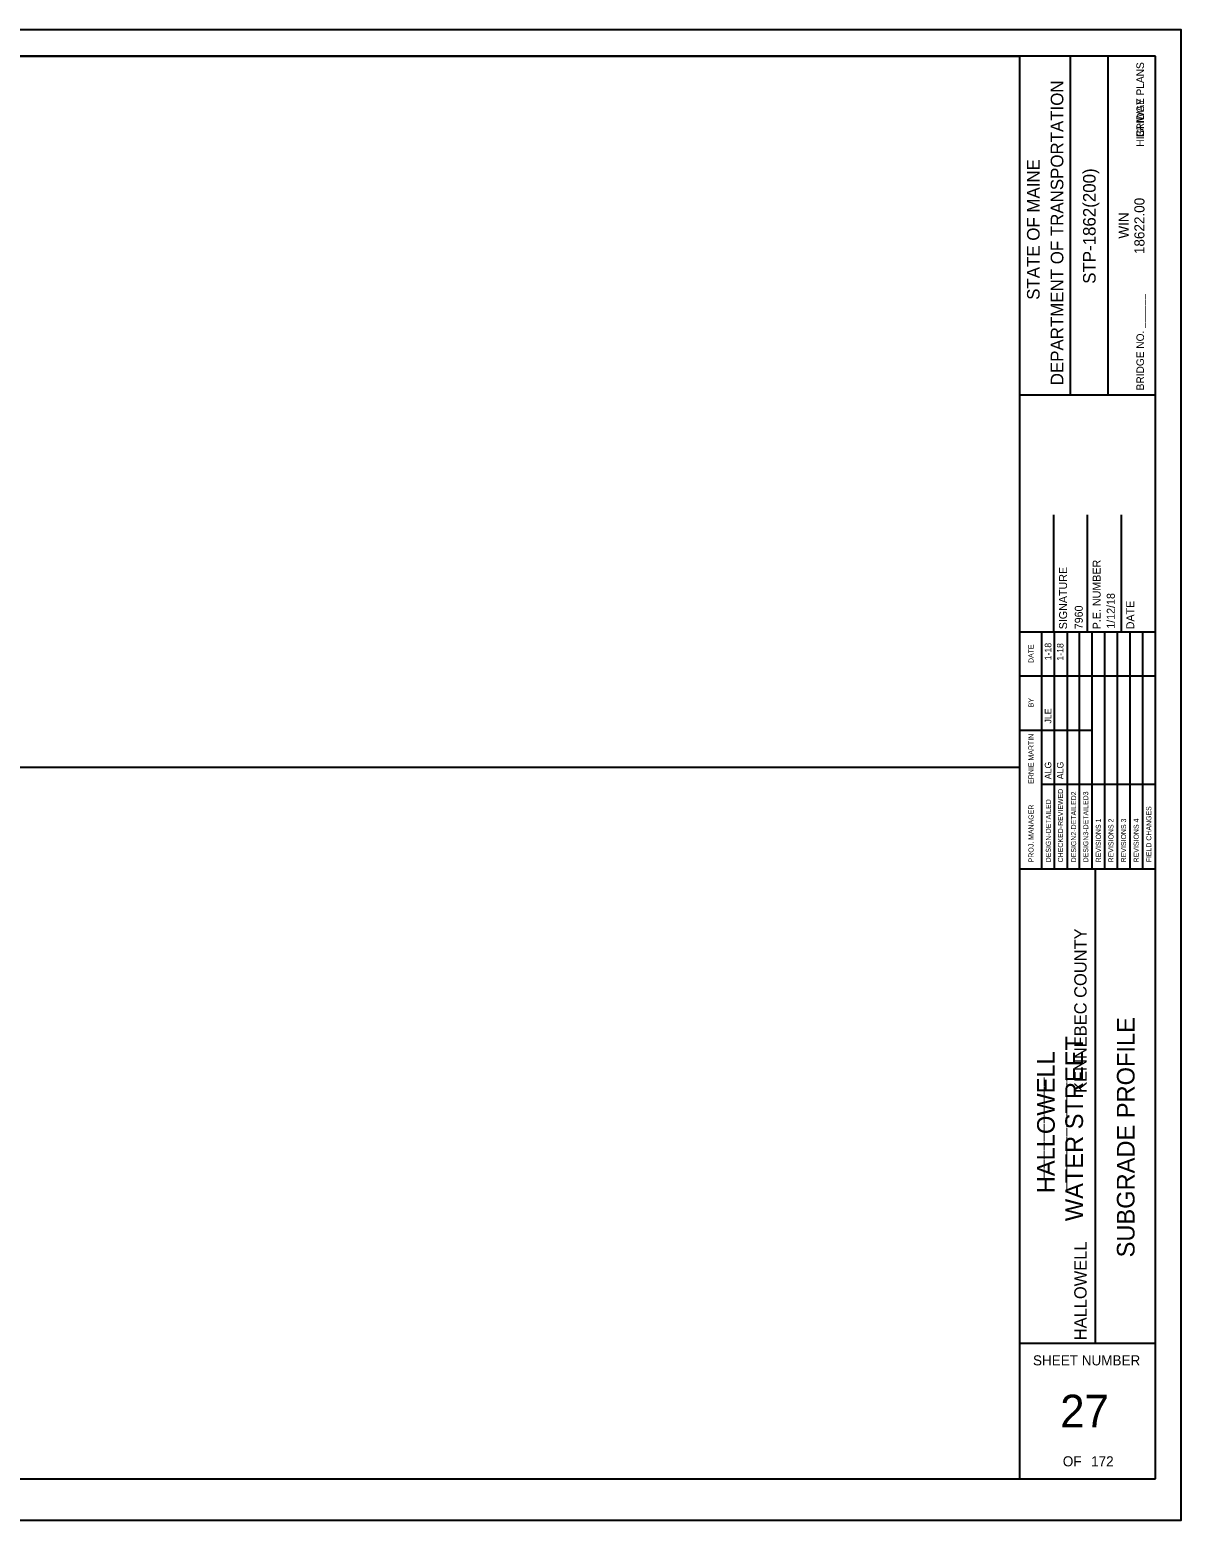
# Model space of a CAD drawing. Extents: x 0 to 850, y 0 to 550.
# Drawn here: x 425 to 850, y 0 to 550 of the extents above; entities that cross this region are included whole.
import ezdxf

# ---------------------------------------------------------------- set-up
doc = ezdxf.new("R2010")
doc.units = 0
for name, color, linetype in [('BORDER', 7, 'Continuous'), ('BRIDGE_TITLE', 7, 'Continuous'), ('Default', 7, 'Continuous'), ('HIGHWAY_TITLE', 7, 'Continuous'), ('PLOT BOUNDARY', 7, 'Continuous')]:
    doc.layers.add(name, color=color, linetype=linetype)

msp = doc.modelspace()

# ---------------------------------------------------------------- linework, layer by layer
at = {"layer": 'BORDER'}
for p, q in [((840.5, 540.32), (40.47, 540.32)), ((790.49, 15.32), (790.49, 540.33)), ((809.14, 415.3), (809.14, 540.3)), ((823.11, 415.3), (823.11, 540.3)), ((840.5, 15.32), (840.5, 540.32)), ((790.5, 415.29), (840.5, 415.29)), ((802.99, 327.83), (802.99, 371.07)), ((815.5, 327.83), (815.5, 371.07)), ((828, 327.83), (828, 371.07)), ((790.49, 327.83), (840.5, 327.83)), ((790.49, 240.33), (840.5, 240.33)), ((818.45, 65.32), (818.45, 240.33)), ((790.49, 65.32), (840.5, 65.32)), ((40.47, 15.3), (840.5, 15.3))]:
    msp.add_line(p, q, dxfattribs=at)
for points in [[(798.57, 311.58), (798.57, 327.83)], [(803.23, 240.34), (803.23, 327.83)], [(807.89, 327.83), (807.89, 240.34)], [(812.55, 240.34), (812.55, 327.83)], [(817.21, 240.34), (817.21, 327.83)], [(821.87, 240.34), (821.87, 327.83)], [(826.52, 240.34), (826.52, 327.83)], [(831.18, 240.34), (831.18, 327.83)], [(835.84, 240.34), (835.84, 327.83)], [(798.57, 240.34), (798.57, 324.3)], [(790.49, 311.58), (840.5, 311.58)], [(790.49, 291.58), (798.57, 291.58)], [(798.57, 291.58), (817.2, 291.58)], [(798.57, 271.58), (840.5, 271.58)]]:
    msp.add_lwpolyline(points, dxfattribs=at)
at = {"layer": 'Default'}
for points in [[(40.47, 540.33), (790.36, 540.33), (790.36, 277.83), (40.47, 277.83)], [(790.49, 277.83), (40.47, 277.83), (40.47, 15.32), (790.49, 15.32)]]:
    msp.add_lwpolyline(points, close=True, dxfattribs=at)
at = {"layer": 'PLOT BOUNDARY'}
msp.add_lwpolyline([(0, 0.01), (850.03, 0.01), (850.03, 550.02), (0, 550.02)], close=True, dxfattribs=at)

# ---------------------------------------------------------------- texts
at = {"layer": 'BORDER'}
for s, height, p in [('DEPARTMENT OF TRANSPORTATION', 4.6589, (806.53, 418.85)), ('STATE OF MAINE', 4.6589, (797.77, 450.38)), ('STP-1862(200)', 4.6589, (818.45, 456.29)), ('18622.00', 3.726, (836.47, 467.25)), ('WIN', 3.726, (830.68, 472.97)), ('P.E. NUMBER', 2.9528, (820.3, 328.79)), ('SIGNATURE', 2.953, (807.9, 328.79)), ('1/12/18', 2.953, (825.52, 328.98)), ('7960', 2.953, (813.7, 328.79)), ('DATE', 2.953, (832.7, 328.79)), ('DATE', 1.857, (795.52, 316.36)), ('1-18', 2.423, (802.11, 317.32)), ('1-18', 2.423, (806.58, 317.2)), ('BY', 1.857, (795.52, 300)), ('JLE', 2.423, (802.11, 294)), ('ERNIE MARTIN', 1.8638, (795.52, 271.78)), ('ALG', 2.423, (802.11, 273.44)), ('ALG', 2.423, (806.58, 273.44)), ('DESIGN-DETAILED', 1.8638, (801.93, 242.77)), ('CHECKED-REVIEWED', 1.8638, (806.4, 242.77)), ('DESIGN2-DETAILED2', 1.8638, (811.24, 242.77)), ('DESIGN3-DETAILED3', 1.8638, (815.72, 242.77)), ('PROJ. MANAGER', 1.8638, (795.52, 242.77)), ('FIELD CHANGES', 1.8638, (839.01, 242.77)), ('REVISIONS 1', 1.8638, (820.38, 242.77)), ('REVISIONS 2', 1.8638, (825.03, 242.77)), ('REVISIONS 3', 1.8638, (829.69, 242.77)), ('REVISIONS 4', 1.8638, (834.35, 242.77)), ('SUBGRADE PROFILE', 6.5216, (832.82, 96.99))]:
    msp.add_text(s, height=height, rotation=90, dxfattribs=at).set_placement(p)
for s, height, p in [('SHEET NUMBER', 3.7265, (795.32, 57.14)), ('27', 12.097, (805.37, 34.22)), ('OF', 3.726, (806.33, 19.87)), ('172', 3.726, (816.78, 19.87))]:
    msp.add_text(s, height=height, dxfattribs=at).set_placement(p)
at = {"layer": 'BRIDGE_TITLE'}
for s, height, p in [('BRIDGE PLANS', 2.7951, (836.29, 510.44)), ('BRIDGE NO. ______', 2.7951, (836.29, 416.97)), ('KENNEBEC COUNTY', 4.5359, (815.1, 157.71)), ('_____________', 4.5359, (806.71, 121.26)), ('___________', 4.5359, (798.33, 126.24)), ('HALLOWELL', 4.536, (815.1, 66.43))]:
    msp.add_text(s, height=height, rotation=90, dxfattribs=at).set_placement(p)
at = {"layer": 'HIGHWAY_TITLE'}
for s, height, p in [('HIGHWAY PLANS', 2.7951, (836.29, 506.89)), ('WATER STREET', 6.5216, (813.79, 110.36)), ('HALLOWELL', 6.522, (803.36, 120.69))]:
    msp.add_text(s, height=height, rotation=90, dxfattribs=at).set_placement(p)

doc.saveas('drawing.dxf')
